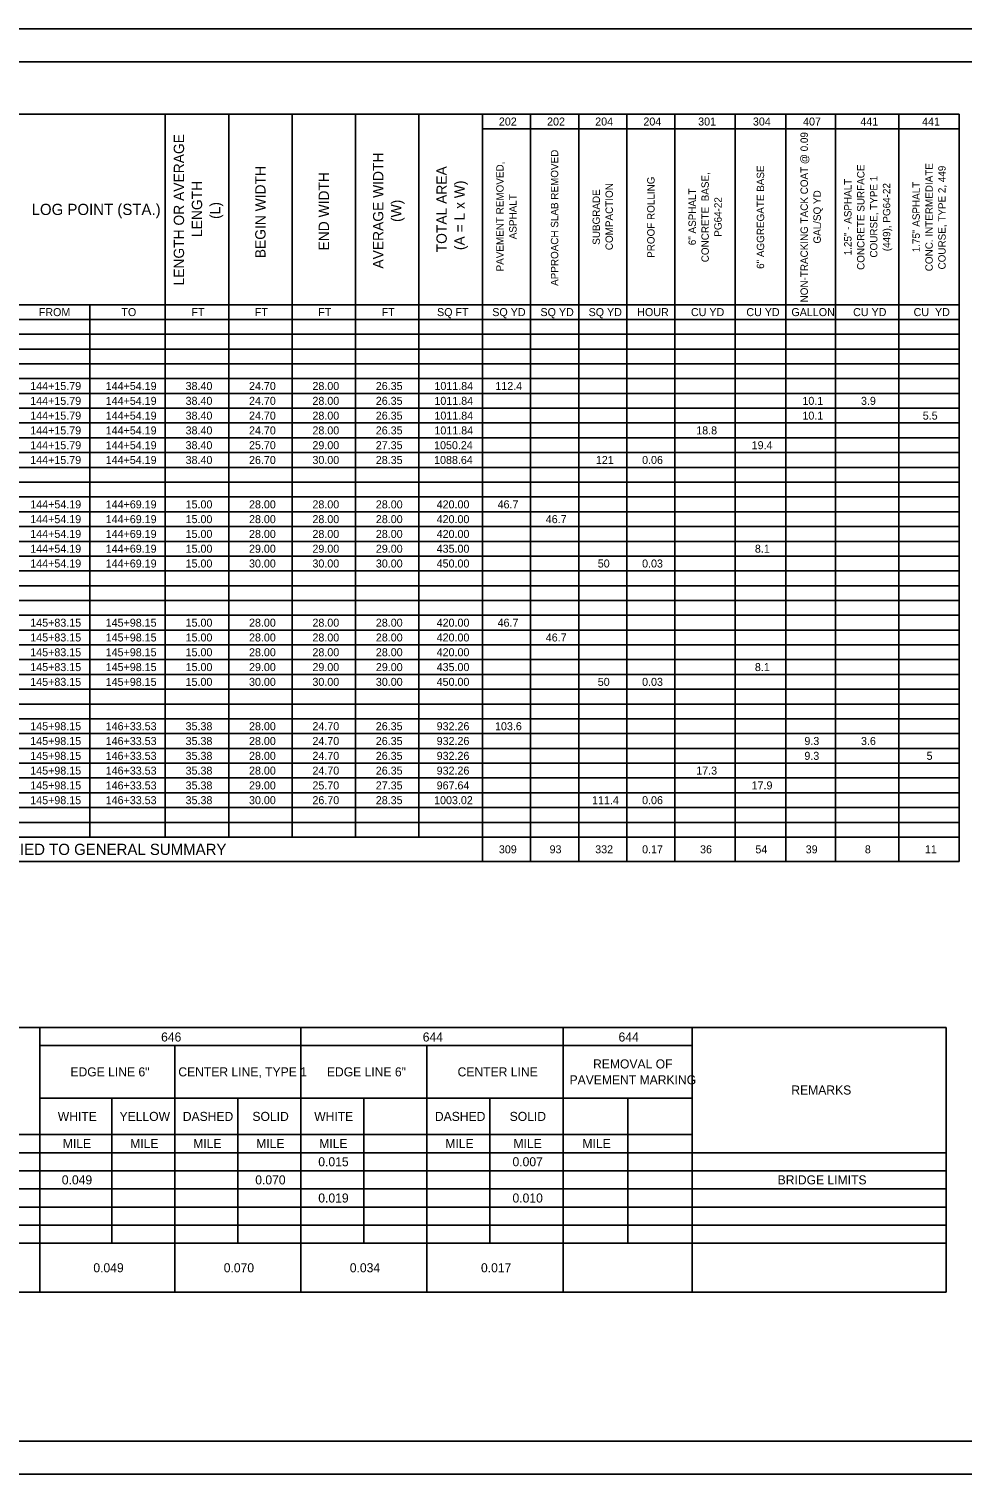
# Model space of a CAD drawing. Extents: x 0 to 34, y 0 to 22.
# Drawn here: x 8.41 to 22.62, y 0 to 22 of the extents above; entities that cross this region are included whole.
import ezdxf

# ---------------------------------------------------------------- set-up
doc = ezdxf.new("R2010")
doc.units = 0
for name, color, linetype in [('SH_Border', 7, 'Continuous'), ('SH_Cut_Line', 7, 'Continuous'), ('SH_Text', 7, 'Continuous')]:
    doc.layers.add(name, color=color, linetype=linetype)

msp = doc.modelspace()

# ---------------------------------------------------------------- linework, layer by layer
at = {"layer": 'SH_Border'}
msp.add_lwpolyline([(1.5, 21.5), (33.5, 21.5), (33.5, 0.5), (1.5, 0.5)], close=True, dxfattribs=at)
at = {"layer": 'SH_Cut_Line'}
msp.add_lwpolyline([(0, 0), (34, 0), (34, 22), (0, 22)], close=True, dxfattribs=at)
at = {"layer": 'SH_Text'}
for p, q in [((2.135, 20.703), (22.576, 20.703)), ((10.485, 20.703), (10.485, 9.696)), ((11.45, 20.703), (11.45, 9.696)), ((12.416, 20.703), (12.416, 9.696)), ((13.382, 20.703), (13.382, 9.696)), ((14.348, 20.703), (14.348, 9.696)), ((15.314, 20.703), (15.314, 9.325)), ((16.047, 20.703), (16.047, 9.325)), ((16.781, 20.703), (16.781, 9.325)), ((17.514, 20.703), (17.514, 9.325)), ((18.248, 20.703), (18.248, 9.325)), ((19.165, 20.703), (19.165, 9.325)), ((19.935, 20.703), (19.935, 9.325)), ((20.693, 20.703), (20.693, 9.325)), ((21.659, 20.703), (21.659, 9.325)), ((22.576, 20.703), (22.576, 9.325)), ((15.314, 20.478), (22.576, 20.478)), ((8.186, 17.802), (22.576, 17.802)), ((9.335, 17.802), (9.335, 9.696)), ((2.135, 17.577), (22.576, 17.577)), ((2.135, 17.352), (22.576, 17.352)), ((2.135, 17.126), (22.576, 17.126)), ((2.135, 16.901), (22.576, 16.901)), ((2.135, 16.676), (22.576, 16.676)), ((2.135, 16.451), (22.576, 16.451)), ((2.135, 16.226), (22.576, 16.226)), ((2.135, 16.001), (22.576, 16.001)), ((2.135, 15.775), (22.576, 15.775)), ((2.135, 15.55), (22.576, 15.55)), ((2.135, 15.325), (22.576, 15.325)), ((2.135, 15.1), (22.576, 15.1)), ((2.135, 14.875), (22.576, 14.875)), ((2.135, 14.65), (22.576, 14.65)), ((2.135, 14.424), (22.576, 14.424)), ((2.135, 14.199), (22.576, 14.199)), ((2.135, 13.974), (22.576, 13.974)), ((2.135, 13.749), (22.576, 13.749)), ((2.135, 13.524), (22.576, 13.524)), ((2.135, 13.299), (22.576, 13.299)), ((2.135, 13.073), (22.576, 13.073)), ((2.135, 12.848), (22.576, 12.848)), ((2.135, 12.623), (22.576, 12.623)), ((2.135, 12.398), (22.576, 12.398)), ((2.135, 12.173), (22.576, 12.173)), ((2.135, 11.948), (22.576, 11.948)), ((2.135, 11.722), (22.576, 11.722)), ((2.135, 11.497), (22.576, 11.497)), ((2.135, 11.272), (22.576, 11.272)), ((2.135, 11.047), (22.576, 11.047)), ((2.135, 10.822), (22.576, 10.822)), ((2.135, 10.597), (22.576, 10.597)), ((2.135, 10.371), (22.576, 10.371)), ((2.135, 10.146), (22.576, 10.146)), ((2.135, 9.921), (22.576, 9.921)), ((2.135, 9.696), (22.576, 9.696)), ((2.135, 9.325), (22.576, 9.325)), ((7.532, 6.801), (8.576, 6.801)), ((8.576, 6.801), (12.548, 6.801)), ((8.576, 6.801), (8.576, 5.997)), ((12.548, 6.801), (22.376, 6.801)), ((12.548, 6.801), (12.548, 6.525)), ((16.544, 6.801), (16.544, 6.525)), ((18.512, 6.801), (18.512, 5.997)), ((22.376, 6.801), (22.376, 5.997)), ((8.576, 6.525), (12.548, 6.525)), ((10.628, 6.525), (10.628, 5.997)), ((12.548, 6.525), (18.512, 6.525)), ((12.548, 6.525), (12.548, 5.997)), ((14.468, 6.525), (14.468, 5.997)), ((16.544, 6.525), (16.544, 5.997)), ((8.576, 5.997), (8.576, 5.169)), ((10.628, 5.997), (10.628, 5.169)), ((12.548, 5.997), (12.548, 5.169)), ((14.468, 5.997), (14.468, 5.169)), ((16.544, 5.997), (16.544, 5.169)), ((18.512, 5.997), (18.512, 5.169)), ((22.376, 5.997), (22.376, 5.169)), ((8.576, 5.721), (12.548, 5.721)), ((9.668, 5.721), (9.668, 5.169)), ((11.588, 5.721), (11.588, 5.169)), ((12.548, 5.721), (18.512, 5.721)), ((13.508, 5.721), (13.508, 5.169)), ((15.428, 5.721), (15.428, 5.169)), ((17.528, 5.721), (17.528, 5.169)), ((7.532, 5.169), (8.576, 5.169)), ((8.576, 5.169), (12.548, 5.169)), ((8.576, 5.169), (8.576, 4.065)), ((9.668, 5.169), (9.668, 4.065)), ((10.628, 5.169), (10.628, 4.065)), ((11.588, 5.169), (11.588, 4.065)), ((12.548, 5.169), (18.512, 5.169)), ((12.548, 5.169), (12.548, 4.065)), ((13.508, 5.169), (13.508, 4.065)), ((14.468, 5.169), (14.468, 4.065)), ((15.428, 5.169), (15.428, 4.065)), ((16.544, 5.169), (16.544, 4.893)), ((17.528, 5.169), (17.528, 4.065)), ((18.512, 5.169), (18.512, 4.065)), ((22.376, 5.169), (22.376, 4.065)), ((7.532, 4.893), (8.576, 4.893)), ((8.576, 4.893), (12.548, 4.893)), ((12.548, 4.893), (22.376, 4.893)), ((16.544, 4.893), (16.544, 4.065)), ((7.532, 4.617), (8.576, 4.617)), ((8.576, 4.617), (12.548, 4.617)), ((12.548, 4.617), (22.376, 4.617)), ((7.532, 4.341), (8.576, 4.341)), ((8.576, 4.341), (12.548, 4.341)), ((12.548, 4.341), (22.376, 4.341)), ((7.532, 4.065), (8.576, 4.065)), ((8.576, 4.065), (12.548, 4.065)), ((8.576, 4.065), (8.576, 3.789)), ((9.668, 4.065), (9.668, 3.789)), ((10.628, 4.065), (10.628, 3.789)), ((11.588, 4.065), (11.588, 3.789)), ((12.548, 4.065), (22.376, 4.065)), ((12.548, 4.065), (12.548, 3.789)), ((13.508, 4.065), (13.508, 3.789)), ((14.468, 4.065), (14.468, 3.789)), ((15.428, 4.065), (15.428, 3.789)), ((16.544, 4.065), (16.544, 3.789)), ((17.528, 4.065), (17.528, 3.789)), ((18.512, 4.065), (18.512, 3.789)), ((22.376, 4.065), (22.376, 3.789)), ((7.532, 3.789), (8.576, 3.789)), ((8.576, 3.789), (12.548, 3.789)), ((8.576, 3.789), (8.576, 2.769)), ((9.668, 3.789), (9.668, 3.513)), ((10.628, 3.789), (10.628, 2.769)), ((11.588, 3.789), (11.588, 3.513)), ((12.548, 3.789), (22.376, 3.789)), ((12.548, 3.789), (12.548, 2.769)), ((13.508, 3.789), (13.508, 3.513)), ((14.468, 3.789), (14.468, 2.769)), ((15.428, 3.789), (15.428, 3.513)), ((16.544, 3.789), (16.544, 2.769)), ((17.528, 3.789), (17.528, 3.513)), ((18.512, 3.789), (18.512, 2.769)), ((22.376, 3.789), (22.376, 2.769)), ((7.532, 3.513), (8.576, 3.513)), ((8.576, 3.513), (12.548, 3.513)), ((12.548, 3.513), (22.376, 3.513)), ((7.532, 2.769), (8.576, 2.769)), ((8.576, 2.769), (12.548, 2.769)), ((12.548, 2.769), (22.376, 2.769))]:
    msp.add_line(p, q, dxfattribs=at)

# ---------------------------------------------------------------- texts
for s, height, p in [('202', 0.1219, (15.566, 20.529)), ('202', 0.1219, (16.3, 20.529)), ('204', 0.1219, (17.033, 20.529)), ('204', 0.1219, (17.767, 20.529)), ('301', 0.1219, (18.601, 20.529)), ('304', 0.1219, (19.435, 20.529)), ('407', 0.1219, (20.199, 20.529)), ('441', 0.1219, (21.071, 20.529)), ('441', 0.1219, (22.012, 20.529)), ('LOG POINT (STA.)', 0.1706, (8.449, 19.167)), ('FROM', 0.1219, (8.558, 17.628)), ('TO', 0.1219, (9.816, 17.628)), ('FT', 0.1219, (10.883, 17.628)), ('FT', 0.1219, (11.848, 17.628)), ('FT', 0.1219, (12.814, 17.628)), ('FT', 0.1219, (13.78, 17.628)), ('SQ FT', 0.1219, (14.624, 17.628)), ('SQ YD', 0.1219, (15.465, 17.628)), ('SQ YD', 0.1219, (16.199, 17.628)), ('SQ YD', 0.1219, (16.932, 17.628)), ('HOUR', 0.1219, (17.673, 17.628)), ('CU YD', 0.1219, (18.491, 17.628)), ('CU YD', 0.1219, (19.335, 17.628)), ('GALLON', 0.1219, (20.021, 17.628)), ('CU YD', 0.1219, (20.961, 17.628)), ('CU  YD', 0.1219, (21.882, 17.628)), ('144+15.79', 0.1219, (8.428, 16.503)), ('144+54.19', 0.1219, (9.577, 16.503)), ('38.40', 0.1219, (10.794, 16.503)), ('24.70', 0.1219, (11.76, 16.503)), ('28.00', 0.1219, (12.726, 16.503)), ('26.35', 0.1219, (13.691, 16.503)), ('1011.84', 0.1219, (14.584, 16.503)), ('112.4', 0.1219, (15.512, 16.503)), ('144+15.79', 0.1219, (8.428, 16.277)), ('144+54.19', 0.1219, (9.577, 16.277)), ('38.40', 0.1219, (10.794, 16.277)), ('24.70', 0.1219, (11.76, 16.277)), ('28.00', 0.1219, (12.726, 16.277)), ('26.35', 0.1219, (13.691, 16.277)), ('1011.84', 0.1219, (14.584, 16.277)), ('10.1', 0.1219, (20.189, 16.277)), ('3.9', 0.1219, (21.081, 16.277)), ('144+15.79', 0.1219, (8.428, 16.052)), ('144+54.19', 0.1219, (9.577, 16.052)), ('38.40', 0.1219, (10.794, 16.052)), ('24.70', 0.1219, (11.76, 16.052)), ('28.00', 0.1219, (12.726, 16.052)), ('26.35', 0.1219, (13.691, 16.052)), ('1011.84', 0.1219, (14.584, 16.052)), ('10.1', 0.1219, (20.189, 16.052)), ('5.5', 0.1219, (22.022, 16.052)), ('144+15.79', 0.1219, (8.428, 15.827)), ('144+54.19', 0.1219, (9.577, 15.827)), ('38.40', 0.1219, (10.794, 15.827)), ('24.70', 0.1219, (11.76, 15.827)), ('28.00', 0.1219, (12.726, 15.827)), ('26.35', 0.1219, (13.691, 15.827)), ('1011.84', 0.1219, (14.584, 15.827)), ('18.8', 0.1219, (18.572, 15.827)), ('144+15.79', 0.1219, (8.428, 15.602)), ('144+54.19', 0.1219, (9.577, 15.602)), ('38.40', 0.1219, (10.794, 15.602)), ('25.70', 0.1219, (11.76, 15.602)), ('29.00', 0.1219, (12.726, 15.602)), ('27.35', 0.1219, (13.691, 15.602)), ('1050.24', 0.1219, (14.579, 15.602)), ('19.4', 0.1219, (19.416, 15.602)), ('144+15.79', 0.1219, (8.428, 15.377)), ('144+54.19', 0.1219, (9.577, 15.377)), ('38.40', 0.1219, (10.794, 15.377)), ('26.70', 0.1219, (11.76, 15.377)), ('30.00', 0.1219, (12.726, 15.377)), ('28.35', 0.1219, (13.691, 15.377)), ('1088.64', 0.1219, (14.579, 15.377)), ('121', 0.1219, (17.043, 15.377)), ('0.06', 0.1219, (17.747, 15.377)), ('144+54.19', 0.1219, (8.428, 14.701)), ('144+69.19', 0.1219, (9.577, 14.701)), ('15.00', 0.1219, (10.794, 14.701)), ('28.00', 0.1219, (11.76, 14.701)), ('28.00', 0.1219, (12.726, 14.701)), ('28.00', 0.1219, (13.692, 14.701)), ('420.00', 0.1219, (14.618, 14.701)), ('46.7', 0.1219, (15.546, 14.701)), ('144+54.19', 0.1219, (8.428, 14.476)), ('144+69.19', 0.1219, (9.577, 14.476)), ('15.00', 0.1219, (10.794, 14.476)), ('28.00', 0.1219, (11.76, 14.476)), ('28.00', 0.1219, (12.726, 14.476)), ('28.00', 0.1219, (13.692, 14.476)), ('420.00', 0.1219, (14.618, 14.476)), ('46.7', 0.1219, (16.28, 14.476)), ('144+54.19', 0.1219, (8.428, 14.251)), ('144+69.19', 0.1219, (9.577, 14.251)), ('15.00', 0.1219, (10.794, 14.251)), ('28.00', 0.1219, (11.76, 14.251)), ('28.00', 0.1219, (12.726, 14.251)), ('28.00', 0.1219, (13.692, 14.251)), ('420.00', 0.1219, (14.618, 14.251)), ('144+54.19', 0.1219, (8.428, 14.026)), ('144+69.19', 0.1219, (9.577, 14.026)), ('15.00', 0.1219, (10.794, 14.026)), ('29.00', 0.1219, (11.76, 14.026)), ('29.00', 0.1219, (12.726, 14.026)), ('29.00', 0.1219, (13.692, 14.026)), ('435.00', 0.1219, (14.618, 14.026)), ('8.1', 0.1219, (19.465, 14.026)), ('144+54.19', 0.1219, (8.428, 13.801)), ('144+69.19', 0.1219, (9.577, 13.801)), ('15.00', 0.1219, (10.794, 13.801)), ('30.00', 0.1219, (11.76, 13.801)), ('30.00', 0.1219, (12.726, 13.801)), ('30.00', 0.1219, (13.692, 13.801)), ('450.00', 0.1219, (14.618, 13.801)), ('50', 0.1219, (17.072, 13.801)), ('0.03', 0.1219, (17.747, 13.801)), ('145+83.15', 0.1219, (8.428, 12.9)), ('145+98.15', 0.1219, (9.577, 12.9)), ('15.00', 0.1219, (10.794, 12.9)), ('28.00', 0.1219, (11.76, 12.9)), ('28.00', 0.1219, (12.726, 12.9)), ('28.00', 0.1219, (13.692, 12.9)), ('420.00', 0.1219, (14.618, 12.9)), ('46.7', 0.1219, (15.546, 12.9)), ('145+83.15', 0.1219, (8.428, 12.675)), ('145+98.15', 0.1219, (9.577, 12.675)), ('15.00', 0.1219, (10.794, 12.675)), ('28.00', 0.1219, (11.76, 12.675)), ('28.00', 0.1219, (12.726, 12.675)), ('28.00', 0.1219, (13.692, 12.675)), ('420.00', 0.1219, (14.618, 12.675)), ('46.7', 0.1219, (16.28, 12.675)), ('145+83.15', 0.1219, (8.428, 12.45)), ('145+98.15', 0.1219, (9.577, 12.45)), ('15.00', 0.1219, (10.794, 12.45)), ('28.00', 0.1219, (11.76, 12.45)), ('28.00', 0.1219, (12.726, 12.45)), ('28.00', 0.1219, (13.692, 12.45)), ('420.00', 0.1219, (14.618, 12.45)), ('145+83.15', 0.1219, (8.428, 12.224)), ('145+98.15', 0.1219, (9.577, 12.224)), ('15.00', 0.1219, (10.794, 12.224)), ('29.00', 0.1219, (11.76, 12.224)), ('29.00', 0.1219, (12.726, 12.224)), ('29.00', 0.1219, (13.692, 12.224)), ('435.00', 0.1219, (14.618, 12.224)), ('8.1', 0.1219, (19.465, 12.224)), ('145+83.15', 0.1219, (8.428, 11.999)), ('145+98.15', 0.1219, (9.577, 11.999)), ('15.00', 0.1219, (10.794, 11.999)), ('30.00', 0.1219, (11.76, 11.999)), ('30.00', 0.1219, (12.726, 11.999)), ('30.00', 0.1219, (13.692, 11.999)), ('450.00', 0.1219, (14.618, 11.999)), ('50', 0.1219, (17.072, 11.999)), ('0.03', 0.1219, (17.747, 11.999)), ('145+98.15', 0.1219, (8.428, 11.324)), ('146+33.53', 0.1219, (9.577, 11.324)), ('35.38', 0.1219, (10.794, 11.324)), ('28.00', 0.1219, (11.76, 11.324)), ('24.70', 0.1219, (12.726, 11.324)), ('26.35', 0.1219, (13.691, 11.324)), ('932.26', 0.1219, (14.618, 11.324)), ('103.6', 0.1219, (15.507, 11.324)), ('145+98.15', 0.1219, (8.428, 11.099)), ('146+33.53', 0.1219, (9.577, 11.099)), ('35.38', 0.1219, (10.794, 11.099)), ('28.00', 0.1219, (11.76, 11.099)), ('24.70', 0.1219, (12.726, 11.099)), ('26.35', 0.1219, (13.691, 11.099)), ('932.26', 0.1219, (14.618, 11.099)), ('9.3', 0.1219, (20.219, 11.099)), ('3.6', 0.1219, (21.081, 11.099)), ('145+98.15', 0.1219, (8.428, 10.873)), ('146+33.53', 0.1219, (9.577, 10.873)), ('35.38', 0.1219, (10.794, 10.873)), ('28.00', 0.1219, (11.76, 10.873)), ('24.70', 0.1219, (12.726, 10.873)), ('26.35', 0.1219, (13.691, 10.873)), ('932.26', 0.1219, (14.618, 10.873)), ('9.3', 0.1219, (20.219, 10.873)), ('5', 0.122, (22.081, 10.873)), ('145+98.15', 0.1219, (8.428, 10.648)), ('146+33.53', 0.1219, (9.577, 10.648)), ('35.38', 0.1219, (10.794, 10.648)), ('28.00', 0.1219, (11.76, 10.648)), ('24.70', 0.1219, (12.726, 10.648)), ('26.35', 0.1219, (13.691, 10.648)), ('932.26', 0.1219, (14.618, 10.648)), ('17.3', 0.1219, (18.572, 10.648)), ('145+98.15', 0.1219, (8.428, 10.423)), ('146+33.53', 0.1219, (9.577, 10.423)), ('35.38', 0.1219, (10.794, 10.423)), ('29.00', 0.1219, (11.76, 10.423)), ('25.70', 0.1219, (12.726, 10.423)), ('27.35', 0.1219, (13.691, 10.423)), ('967.64', 0.1219, (14.618, 10.423)), ('17.9', 0.1219, (19.415, 10.423)), ('145+98.15', 0.1219, (8.428, 10.198)), ('146+33.53', 0.1219, (9.577, 10.198)), ('35.38', 0.1219, (10.794, 10.198)), ('30.00', 0.1219, (11.76, 10.198)), ('26.70', 0.1219, (12.726, 10.198)), ('28.35', 0.1219, (13.691, 10.198)), ('1003.02', 0.1219, (14.579, 10.198)), ('111.4', 0.1219, (16.985, 10.198)), ('0.06', 0.1219, (17.747, 10.198)), ('TOTALS CARRIED TO GENERAL SUMMARY', 0.1706, (6.675, 9.425)), ('309', 0.1219, (15.566, 9.45)), ('93', 0.1219, (16.338, 9.45)), ('332', 0.1219, (17.033, 9.45)), ('0.17', 0.1219, (17.747, 9.45)), ('36', 0.1219, (18.63, 9.45)), ('54', 0.1219, (19.473, 9.45)), ('39', 0.1219, (20.239, 9.45)), ('8', 0.122, (21.14, 9.45)), ('11', 0.1219, (22.054, 9.45)), ('646', 0.138, (10.421, 6.585)), ('644', 0.138, (14.406, 6.585)), ('644', 0.138, (17.388, 6.585)), ('EDGE LINE 6"', 0.138, (9.04, 6.054)), ('CENTER LINE, TYPE 1', 0.138, (10.683, 6.054)), ('EDGE LINE 6"', 0.138, (12.946, 6.054)), ('CENTER LINE', 0.138, (14.937, 6.054)), (' REMOVAL OF ', 0.138, (16.949, 6.175)), ('PAVEMENT MARKING', 0.138, (16.642, 5.933)), ('REMARKS', 0.138, (20.02, 5.778)), ('WHITE', 0.138, (8.847, 5.376)), ('YELLOW', 0.138, (9.788, 5.376)), ('DASHED', 0.138, (10.751, 5.376)), ('SOLID', 0.138, (11.812, 5.376)), ('WHITE', 0.138, (12.753, 5.376)), ('DASHED', 0.138, (14.591, 5.376)), ('SOLID', 0.138, (15.73, 5.376)), ('MILE', 0.138, (8.924, 4.962)), ('MILE', 0.138, (9.95, 4.962)), ('MILE', 0.138, (10.91, 4.962)), ('MILE', 0.138, (11.87, 4.962)), ('MILE', 0.138, (12.83, 4.962)), ('MILE', 0.138, (14.75, 4.962)), ('MILE', 0.138, (15.788, 4.962)), ('MILE', 0.138, (16.838, 4.962)), ('0.015', 0.138, (12.815, 4.686)), ('0.007', 0.138, (15.773, 4.686)), ('0.049', 0.138, (8.909, 4.41)), ('0.070', 0.138, (11.855, 4.41)), ('BRIDGE LIMITS', 0.138, (19.812, 4.41)), ('0.019', 0.138, (12.815, 4.134)), ('0.010', 0.138, (15.773, 4.134)), ('0.049', 0.138, (9.389, 3.072)), ('0.070', 0.138, (11.375, 3.072)), ('0.034', 0.138, (13.295, 3.072)), ('0.017', 0.138, (15.293, 3.072))]:
    msp.add_text(s, height=height, dxfattribs=at).set_placement(p)
for s, height, p in [('LENGTH OR AVERAGE ', 0.15747, (10.771, 18.094)), ('NON-TRACKING TACK COAT @ 0.09 ', 0.11248, (20.272, 17.836)), ('AVERAGE WIDTH                   ', 0.15747, (13.806, 18.351)), ('APPROACH SLAB REMOVED', 0.11248, (16.47, 18.088)), ('BEGIN WIDTH', 0.15747, (12.012, 18.509)), ('END WIDTH', 0.1575, (12.978, 18.627)), ('TOTAL AREA                       ', 0.15747, (14.772, 18.599)), ('PAVEMENT REMOVED,                                  ', 0.11248, (15.638, 18.308)), ('CONCRETE  BASE,                           ', 0.11248, (18.763, 18.448)), ('6" AGGREGATE BASE', 0.11248, (19.606, 18.347)), ('CONCRETE SURFACE                      ', 0.11248, (21.134, 18.331)), ('CONC. INTERMEDIATE                             ', 0.11248, (22.174, 18.311)), ('COURSE, TYPE 2, 449', 0.11248, (22.37, 18.338)), ('LENGTH                             ', 0.15747, (11.046, 18.832)), ('(A = L x W)', 0.15747, (15.047, 18.633)), ('COMPACTION', 0.1125, (17.302, 18.632)), ('PROOF ROLLING', 0.11248, (17.937, 18.515)), ('1.25" - ASPHALT                                ', 0.11248, (20.937, 18.554)), ('COURSE, TYPE 1                           ', 0.11248, (21.331, 18.519)), ('(449), PG64-22', 0.11248, (21.527, 18.616)), ('1.75" ASPHALT                             ', 0.11248, (21.977, 18.6)), ('(W)', 0.1575, (14.082, 19.061)), ('ASPHALT', 0.1125, (15.835, 18.798)), ('SUBGRADE                                 ', 0.11248, (17.105, 18.714)), ('6" ASPHALT                             ', 0.11248, (18.566, 18.707)), ('PG64-22', 0.1125, (18.959, 18.837)), ('GAL/SQ YD', 0.1125, (20.469, 18.732)), ('(L)', 0.1575, (11.322, 19.107))]:
    msp.add_text(s, height=height, rotation=90, dxfattribs=at).set_placement(p)

doc.saveas('drawing.dxf')
